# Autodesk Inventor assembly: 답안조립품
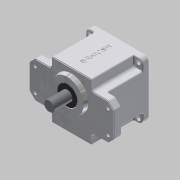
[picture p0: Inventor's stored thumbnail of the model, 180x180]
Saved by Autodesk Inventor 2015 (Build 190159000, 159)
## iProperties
Created: 2016-02
Part Number: 답안조립품
Document SubType Name: Assembly
Designer: Administrator
Author: Administrator
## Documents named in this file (10)
- C:\Users\Administrator\Desktop\460209V1018\답안조립품.iam
- C:\Users\Administrator\Desktop\460209V1018\본체.ipt
- C:\Users\Administrator\Desktop\460209V1018\오일실 17 32 8.ipt
- C:\Users\Administrator\Desktop\460209V1018\베어링 6003.ipt
- C:\Users\Administrator\Desktop\460209V1018\서브축.ipt
- C:\Users\Administrator\Desktop\460209V1018\베어링 608.ipt
- C:\Users\Administrator\Desktop\460209V1018\커버.ipt
- C:\Users\Administrator\Desktop\460209V1018\볼트 M4 x 10.ipt
- C:\Users\Administrator\Desktop\460209V1018\메인축.ipt
- C:\Users\Administrator\Desktop\460209V1018\오일실 8 22 7.ipt
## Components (2 placed, 1 different names)
1. ISO 4762 M4 x 10:1 — Insert:1
2. ISO 4762 M4 x 10:2
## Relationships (1: Insert 1)
- Insert:1: ISO 4762 M4 x 10:1
